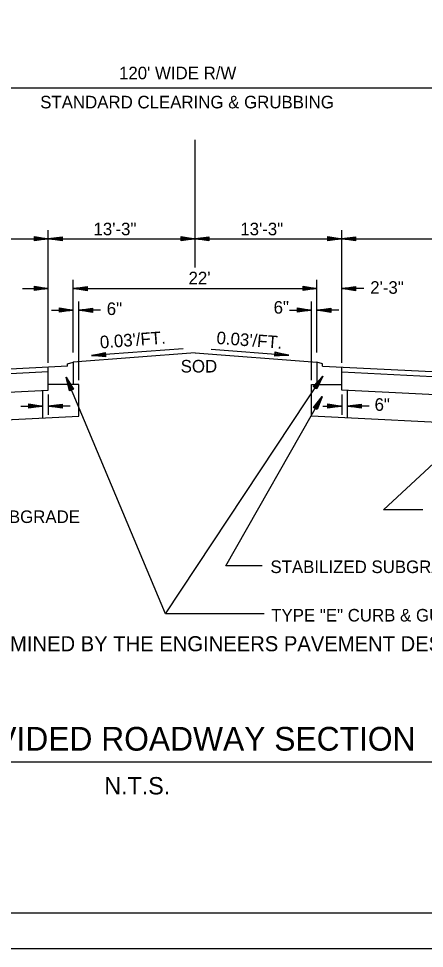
# Model space of a CAD drawing. Extents: x 29.7 to 46.4, y -39.2 to -28.2.
# Drawn here: x 34.11 to 36.79, y -39.2 to -33.04 of the extents above; entities that cross this region are included whole.
import ezdxf

# ---------------------------------------------------------------- set-up
doc = ezdxf.new("R2010")
doc.units = 0
for name, color, linetype in [('Level 1', 7, 'Continuous'), ('Level 10', 7, 'Continuous'), ('Level 4', 7, 'Continuous'), ('Level 60', 7, 'Continuous'), ('Level 8', 7, 'Continuous'), ('Level 9', 7, 'Continuous')]:
    doc.layers.add(name, color=color, linetype=linetype)

msp = doc.modelspace()

# ---------------------------------------------------------------- linework, layer by layer
at = {"layer": 'Level 4'}
msp.add_line((37.3605, -37.9659), (32.8081, -37.9659), dxfattribs=at)
at = {"layer": 'Level 60'}
for points in [[(29.7027, -39.1993), (46.0327, -39.1993), (46.0327, -28.1926), (29.7027, -28.1926)], [(30.3565, -28.4094), (45.7818, -28.4094), (45.7818, -38.965), (30.3565, -38.965)]]:
    msp.add_lwpolyline(points, close=True, dxfattribs=at)
at = {"layer": 'Level 8'}
for p, q in [((30.8765, -33.4948), (39.6765, -33.4948)), ((35.2765, -34.686), (35.2765, -33.8391)), ((34.3048, -35.3175), (34.3048, -34.4376)), ((36.2481, -35.3175), (36.2481, -34.4376)), ((32.3981, -34.4953), (34.3048, -34.4953)), ((34.3048, -34.4953), (35.2765, -34.4953)), ((35.2765, -34.4953), (36.2481, -34.4953)), ((36.2481, -34.4953), (38.1548, -34.4953)), ((34.4698, -35.2496), (34.4698, -34.7673)), ((36.0831, -35.2496), (36.0831, -34.7673)), ((34.1351, -34.825), (34.3048, -34.825)), ((34.4698, -34.825), (36.0831, -34.825)), ((36.3948, -34.825), (36.2481, -34.825)), ((34.5065, -35.433), (34.5065, -34.9108)), ((36.0465, -35.433), (36.0465, -34.9108)), ((34.3254, -34.9686), (34.4698, -34.9686)), ((34.6508, -34.9686), (34.5065, -34.9686)), ((35.9021, -34.9686), (36.0465, -34.9686)), ((36.2275, -34.9686), (36.0831, -34.9686)), ((35.2765, -35.2525), (34.4698, -35.313)), ((35.1977, -35.2242), (34.591, -35.2697)), ((35.2765, -35.2525), (36.0831, -35.313)), ((35.3831, -35.2277), (35.8981, -35.2663)), ((34.4331, -35.3241), (34.4698, -35.313)), ((36.1198, -35.3241), (36.0831, -35.313)), ((34.4331, -35.3399), (32.3981, -35.4417)), ((34.3048, -35.3776), (32.3981, -35.4729)), ((34.4331, -35.3399), (34.4331, -35.3241)), ((36.1198, -35.3399), (36.1198, -35.3241)), ((36.1198, -35.3399), (38.1548, -35.4417)), ((36.2481, -35.3776), (38.1548, -35.4729)), ((35.08, -36.9817), (36.1221, -35.406)), ((34.2681, -35.6841), (34.2681, -35.5005)), ((36.2848, -35.6841), (36.2848, -35.5005)), ((34.3048, -35.5276), (34.3048, -35.6622)), ((36.2481, -35.5276), (36.2481, -35.6622)), ((34.1238, -35.6044), (34.2681, -35.6044)), ((34.4491, -35.6044), (34.3048, -35.6044)), ((36.1221, -35.6044), (36.2481, -35.6044)), ((36.4291, -35.6044), (36.2848, -35.6044))]:
    msp.add_line(p, q, dxfattribs=at)
for points in [[(34.4698, -35.313), (34.4698, -35.4619), (34.3048, -35.4619), (34.3048, -35.3464)], [(36.0831, -35.313), (36.0831, -35.4619), (36.2481, -35.4619), (36.2481, -35.3464)], [(35.7337, -36.9817), (35.08, -36.9817), (34.4229, -35.4123)], [(32.2515, -35.5572), (32.2148, -35.5572), (32.2148, -35.7868), (34.5065, -35.6722), (34.5065, -35.4619), (34.4698, -35.4619)], [(32.3981, -35.5572), (32.3981, -35.594), (34.3048, -35.4987), (34.3048, -35.4619)], [(38.3015, -35.5572), (38.3381, -35.5572), (38.3381, -35.7868), (36.0465, -35.6722), (36.0465, -35.4619), (36.0831, -35.4619)], [(38.1548, -35.5572), (38.1548, -35.594), (36.2481, -35.4987), (36.2481, -35.4619)], [(35.7215, -36.6637), (35.4812, -36.6637), (36.1182, -35.5414)], [(36.7845, -36.2929), (36.5246, -36.2929), (37.189, -35.6752)]]:
    msp.add_lwpolyline(points, dxfattribs=at)
at = {"layer": 'Level 9'}
for p, q in [((34.2132, -34.509), (34.2132, -34.4807)), ((34.2132, -34.4807), (34.3046, -34.4956)), ((34.3043, -34.4959), (34.2132, -34.509)), ((34.3048, -34.4953), (34.2133, -34.4862)), ((34.2133, -34.4862), (34.2133, -34.4999)), ((34.2133, -34.4953), (34.2133, -34.4908)), ((34.2133, -34.4908), (34.3048, -34.4953)), ((34.2133, -34.5045), (34.3048, -34.4953)), ((34.3048, -34.4953), (34.2133, -34.4953)), ((34.2133, -34.4999), (34.3002, -34.4953)), ((34.3963, -34.4862), (34.3048, -34.4953)), ((34.3048, -34.4953), (34.3963, -34.4953)), ((34.3963, -34.4999), (34.3048, -34.4953)), ((34.3048, -34.4953), (34.3963, -34.5045)), ((34.3964, -34.51), (34.3049, -34.4951)), ((34.3053, -34.4947), (34.3964, -34.4816)), ((34.3963, -34.4908), (34.3094, -34.4953)), ((34.3963, -34.5045), (34.3963, -34.4908)), ((34.3963, -34.4953), (34.3963, -34.4999)), ((34.3964, -34.4816), (34.3964, -34.51)), ((35.1849, -34.509), (35.1849, -34.4807)), ((35.1849, -34.4807), (35.2763, -34.4956)), ((35.2765, -34.4953), (35.1849, -34.4862)), ((35.1849, -34.4862), (35.1849, -34.4999)), ((35.1849, -34.4953), (35.1849, -34.4908)), ((35.1849, -34.4908), (35.2765, -34.4953)), ((35.1849, -34.5045), (35.2765, -34.4953)), ((35.2765, -34.4953), (35.1849, -34.4953)), ((35.1849, -34.4999), (35.2719, -34.4953)), ((35.276, -34.4959), (35.1849, -34.509)), ((35.368, -34.4862), (35.2765, -34.4953)), ((35.2765, -34.4953), (35.368, -34.4953)), ((35.368, -34.4999), (35.2765, -34.4953)), ((35.2765, -34.4953), (35.368, -34.5045)), ((35.368, -34.51), (35.2766, -34.4951)), ((35.2769, -34.4947), (35.368, -34.4816)), ((35.368, -34.4908), (35.281, -34.4953)), ((35.368, -34.4816), (35.368, -34.51)), ((35.368, -34.5045), (35.368, -34.4908)), ((35.368, -34.4953), (35.368, -34.4999)), ((36.1565, -34.509), (36.1565, -34.4807)), ((36.1565, -34.4807), (36.248, -34.4956)), ((36.2477, -34.4959), (36.1565, -34.509)), ((36.2481, -34.4953), (36.1566, -34.4862)), ((36.1566, -34.4862), (36.1566, -34.4999)), ((36.1566, -34.4953), (36.1566, -34.4908)), ((36.1566, -34.4908), (36.2481, -34.4953)), ((36.1566, -34.5045), (36.2481, -34.4953)), ((36.2481, -34.4953), (36.1566, -34.4953)), ((36.1566, -34.4999), (36.2435, -34.4953)), ((36.3396, -34.4862), (36.2481, -34.4953)), ((36.2481, -34.4953), (36.3396, -34.4953)), ((36.3396, -34.4999), (36.2481, -34.4953)), ((36.2481, -34.4953), (36.3396, -34.5045)), ((36.3397, -34.51), (36.2483, -34.4951)), ((36.2486, -34.4947), (36.3397, -34.4816)), ((36.3396, -34.4908), (36.2527, -34.4953)), ((36.3396, -34.5045), (36.3396, -34.4908)), ((36.3396, -34.4953), (36.3396, -34.4999)), ((36.3397, -34.4816), (36.3397, -34.51)), ((34.2132, -34.8387), (34.2132, -34.8104)), ((34.2132, -34.8104), (34.3046, -34.8253)), ((34.3048, -34.825), (34.2133, -34.8159)), ((34.2133, -34.8159), (34.2133, -34.8296)), ((34.2133, -34.825), (34.2133, -34.8204)), ((34.2133, -34.8204), (34.3048, -34.825)), ((34.5613, -34.8159), (34.4698, -34.825)), ((34.4703, -34.8244), (34.5614, -34.8113)), ((34.5613, -34.8204), (34.4744, -34.825)), ((34.5613, -34.8342), (34.5613, -34.8204)), ((34.5614, -34.8113), (34.5614, -34.8397)), ((35.9915, -34.8387), (35.9915, -34.8104)), ((35.9915, -34.8104), (36.083, -34.8253)), ((36.0831, -34.825), (35.9916, -34.8159)), ((35.9916, -34.8159), (35.9916, -34.8296)), ((35.9916, -34.825), (35.9916, -34.8204)), ((35.9916, -34.8204), (36.0831, -34.825)), ((36.3396, -34.8159), (36.2481, -34.825)), ((36.2486, -34.8244), (36.3397, -34.8113)), ((36.3396, -34.8204), (36.2527, -34.825)), ((36.3396, -34.8342), (36.3396, -34.8204)), ((36.3397, -34.8113), (36.3397, -34.8397)), ((34.3043, -34.8256), (34.2132, -34.8387)), ((34.2133, -34.8342), (34.3048, -34.825)), ((34.3048, -34.825), (34.2133, -34.825)), ((34.2133, -34.8296), (34.3002, -34.825)), ((34.4698, -34.825), (34.5613, -34.825)), ((34.5613, -34.8296), (34.4698, -34.825)), ((34.4698, -34.825), (34.5613, -34.8342)), ((34.5614, -34.8397), (34.4699, -34.8248)), ((34.5613, -34.825), (34.5613, -34.8296)), ((36.0827, -34.8256), (35.9915, -34.8387)), ((35.9916, -34.8342), (36.0831, -34.825)), ((36.0831, -34.825), (35.9916, -34.825)), ((35.9916, -34.8296), (36.0785, -34.825)), ((36.2481, -34.825), (36.3396, -34.825)), ((36.3396, -34.8296), (36.2481, -34.825)), ((36.2481, -34.825), (36.3396, -34.8342)), ((36.3397, -34.8397), (36.2483, -34.8248)), ((36.3396, -34.825), (36.3396, -34.8296)), ((34.3782, -34.9823), (34.3782, -34.9539)), ((34.3782, -34.9539), (34.4696, -34.9688)), ((34.4693, -34.9692), (34.3782, -34.9823)), ((34.4698, -34.9686), (34.3783, -34.9594)), ((34.3783, -34.9594), (34.3783, -34.9731)), ((34.3783, -34.9686), (34.3783, -34.964)), ((34.3783, -34.964), (34.4698, -34.9686)), ((34.3783, -34.9777), (34.4698, -34.9686)), ((34.4698, -34.9686), (34.3783, -34.9686)), ((34.3783, -34.9731), (34.4652, -34.9686)), ((34.598, -34.9594), (34.5065, -34.9686)), ((34.5065, -34.9686), (34.598, -34.9686)), ((34.598, -34.9731), (34.5065, -34.9686)), ((34.5065, -34.9686), (34.598, -34.9777)), ((34.598, -34.9832), (34.5066, -34.9683)), ((34.5069, -34.968), (34.598, -34.9549)), ((34.598, -34.964), (34.511, -34.9686)), ((34.598, -34.9549), (34.598, -34.9832)), ((34.598, -34.9777), (34.598, -34.964)), ((34.598, -34.9686), (34.598, -34.9731)), ((35.9549, -34.9823), (35.9549, -34.9539)), ((35.9549, -34.9539), (36.0463, -34.9688)), ((36.0465, -34.9686), (35.9549, -34.9594)), ((35.9549, -34.9594), (35.9549, -34.9731)), ((35.9549, -34.9686), (35.9549, -34.964)), ((35.9549, -34.964), (36.0465, -34.9686)), ((35.9549, -34.9777), (36.0465, -34.9686)), ((36.0465, -34.9686), (35.9549, -34.9686)), ((35.9549, -34.9731), (36.0419, -34.9686)), ((36.046, -34.9692), (35.9549, -34.9823)), ((36.1746, -34.9594), (36.0831, -34.9686)), ((36.0831, -34.9686), (36.1746, -34.9686)), ((36.1746, -34.9731), (36.0831, -34.9686)), ((36.0831, -34.9686), (36.1746, -34.9777)), ((36.1747, -34.9832), (36.0833, -34.9683)), ((36.0836, -34.968), (36.1747, -34.9549)), ((36.1746, -34.964), (36.0877, -34.9686)), ((36.1746, -34.9777), (36.1746, -34.964)), ((36.1746, -34.9686), (36.1746, -34.9731)), ((36.1747, -34.9549), (36.1747, -34.9832)), ((34.6816, -35.2538), (34.591, -35.2697)), ((34.5914, -35.2691), (34.6813, -35.2492)), ((34.6813, -35.2492), (34.6834, -35.2775)), ((35.8058, -35.2731), (35.8079, -35.2449)), ((35.8076, -35.2504), (35.8065, -35.264)), ((35.8981, -35.2663), (35.8076, -35.2504)), ((35.8079, -35.2449), (35.898, -35.2666)), ((34.591, -35.2697), (34.6823, -35.2629)), ((34.6826, -35.2674), (34.591, -35.2697)), ((34.591, -35.2697), (34.6829, -35.272)), ((34.6834, -35.2775), (34.5911, -35.2694)), ((34.6819, -35.2583), (34.5956, -35.2694)), ((34.6829, -35.272), (34.6819, -35.2583)), ((34.6823, -35.2629), (34.6826, -35.2674)), ((35.8976, -35.2669), (35.8058, -35.2731)), ((35.8062, -35.2686), (35.8981, -35.2663)), ((35.8065, -35.264), (35.8936, -35.266)), ((35.8069, -35.2595), (35.8072, -35.2549)), ((35.8981, -35.2663), (35.8069, -35.2595)), ((35.8072, -35.2549), (35.8981, -35.2663)), ((34.4667, -35.4931), (34.4229, -35.4123)), ((34.4229, -35.4123), (34.4582, -35.4967)), ((34.454, -35.4984), (34.4229, -35.4123)), ((34.4229, -35.4123), (34.4498, -35.5002)), ((34.4447, -35.5024), (34.4232, -35.4123)), ((34.4236, -35.4125), (34.4709, -35.4914)), ((34.4624, -35.4949), (34.4246, -35.4165)), ((36.0594, -35.4743), (36.1223, -35.4063)), ((36.1221, -35.406), (36.064, -35.4773)), ((36.0678, -35.4798), (36.1221, -35.406)), ((36.1221, -35.406), (36.0716, -35.4823)), ((36.0754, -35.4848), (36.1196, -35.4098)), ((36.0793, -35.4874), (36.1221, -35.406)), ((36.1224, -35.4067), (36.083, -35.4899)), ((34.4709, -35.4914), (34.4447, -35.5024)), ((34.4498, -35.5002), (34.4624, -35.4949)), ((34.4582, -35.4967), (34.454, -35.4984)), ((36.083, -35.4899), (36.0594, -35.4743)), ((36.064, -35.4773), (36.0754, -35.4848)), ((36.0716, -35.4823), (36.0678, -35.4798)), ((36.0602, -35.6139), (36.1183, -35.5417)), ((36.1182, -35.5414), (36.0651, -35.6165)), ((36.069, -35.6188), (36.1182, -35.5414)), ((36.1182, -35.5414), (36.073, -35.621)), ((36.077, -35.6233), (36.1159, -35.5454)), ((36.081, -35.6255), (36.1182, -35.5414)), ((36.1185, -35.5421), (36.0849, -35.6278)), ((34.1765, -35.6181), (34.1765, -35.5898)), ((34.1765, -35.5898), (34.268, -35.6047)), ((34.2677, -35.605), (34.1765, -35.6181)), ((34.2681, -35.6044), (34.1766, -35.5953)), ((34.1766, -35.5953), (34.1766, -35.609)), ((34.1766, -35.6044), (34.1766, -35.5999)), ((34.1766, -35.5999), (34.2681, -35.6044)), ((34.1766, -35.6136), (34.2681, -35.6044)), ((34.2681, -35.6044), (34.1766, -35.6044)), ((34.1766, -35.609), (34.2635, -35.6044)), ((34.3963, -35.5953), (34.3048, -35.6044)), ((34.3048, -35.6044), (34.3963, -35.6044)), ((34.3963, -35.609), (34.3048, -35.6044)), ((34.3048, -35.6044), (34.3963, -35.6136)), ((34.3964, -35.6191), (34.3049, -35.6042)), ((34.3053, -35.6038), (34.3964, -35.5908)), ((34.3963, -35.5999), (34.3094, -35.6044)), ((34.3963, -35.6136), (34.3963, -35.5999)), ((34.3963, -35.6044), (34.3963, -35.609)), ((34.3964, -35.5908), (34.3964, -35.6191)), ((36.0849, -35.6278), (36.0602, -35.6139)), ((36.0651, -35.6165), (36.077, -35.6233)), ((36.073, -35.621), (36.069, -35.6188)), ((36.1565, -35.6181), (36.1565, -35.5898)), ((36.1565, -35.5898), (36.248, -35.6047)), ((36.2477, -35.605), (36.1565, -35.6181)), ((36.2481, -35.6044), (36.1566, -35.5953)), ((36.1566, -35.5953), (36.1566, -35.609)), ((36.1566, -35.6044), (36.1566, -35.5999)), ((36.1566, -35.5999), (36.2481, -35.6044)), ((36.1566, -35.6136), (36.2481, -35.6044)), ((36.2481, -35.6044), (36.1566, -35.6044)), ((36.1566, -35.609), (36.2435, -35.6044)), ((36.3763, -35.5953), (36.2848, -35.6044)), ((36.2848, -35.6044), (36.3763, -35.6044)), ((36.3763, -35.609), (36.2848, -35.6044)), ((36.2848, -35.6044), (36.3763, -35.6136)), ((36.3764, -35.6191), (36.2849, -35.6042)), ((36.2853, -35.6038), (36.3764, -35.5908)), ((36.3763, -35.5999), (36.2894, -35.6044)), ((36.3763, -35.6136), (36.3763, -35.5999)), ((36.3763, -35.6044), (36.3763, -35.609)), ((36.3764, -35.5908), (36.3764, -35.6191))]:
    msp.add_line(p, q, dxfattribs=at)

# ---------------------------------------------------------------- texts
at = {"layer": 'Level 1'}
msp.add_text('FINAL LAYER THICKNESSES TO BE DETERMINED BY THE ENGINEERS PAVEMENT DESIGN CALCULATIONS.', height=0.1, dxfattribs=at).set_placement((31.2874, -37.2297))
at = {"layer": 'Level 10'}
for s, height, p in [('TYPICAL DIVIDED ROADWAY SECTION', 0.157302, (32.8088, -37.8884)), ('N.T.S.', 0.1152, (34.6757, -38.1788))]:
    msp.add_text(s, height=height, dxfattribs=at).set_placement(p)
at = {"layer": 'Level 8'}
for s, height, p in [("120' WIDE R/W", 0.083333, (34.7732, -33.4382)), ('STANDARD CLEARING & GRUBBING', 0.083333, (34.2515, -33.6311)), ('13\'-3"', 0.08333, (34.6044, -34.4722)), ('13\'-3"', 0.08333, (35.576, -34.4722)), ("22'", 0.08333, (35.2336, -34.7974)), ('2\'-3"', 0.08333, (36.4363, -34.8601)), ('6"', 0.08333, (34.6919, -35.0008)), ('6"', 0.08333, (35.7968, -34.9917)), ('SOD', 0.08333, (35.1816, -35.3819)), ('6"', 0.08333, (36.4651, -35.6358)), ('MINIMUM 12" COMPACTED SUBGRADE', 0.083333, (32.4197, -36.3795)), ('STABILIZED SUBGRADE LBR 40, TYP.', 0.083333, (35.7755, -36.7114)), ('TYPE "E" CURB & GUTTER', 0.083333, (35.7808, -37.0325))]:
    msp.add_text(s, height=height, dxfattribs=at).set_placement(p)
for rotation, p in [(4.28915, (34.6498, -35.223)), (355.71084, (35.4163, -35.1923))]:
    msp.add_text("0.03'/FT.", height=0.08333, rotation=rotation, dxfattribs=at).set_placement(p)

doc.saveas('drawing.dxf')
